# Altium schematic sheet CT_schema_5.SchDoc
size 308 x 315 mm
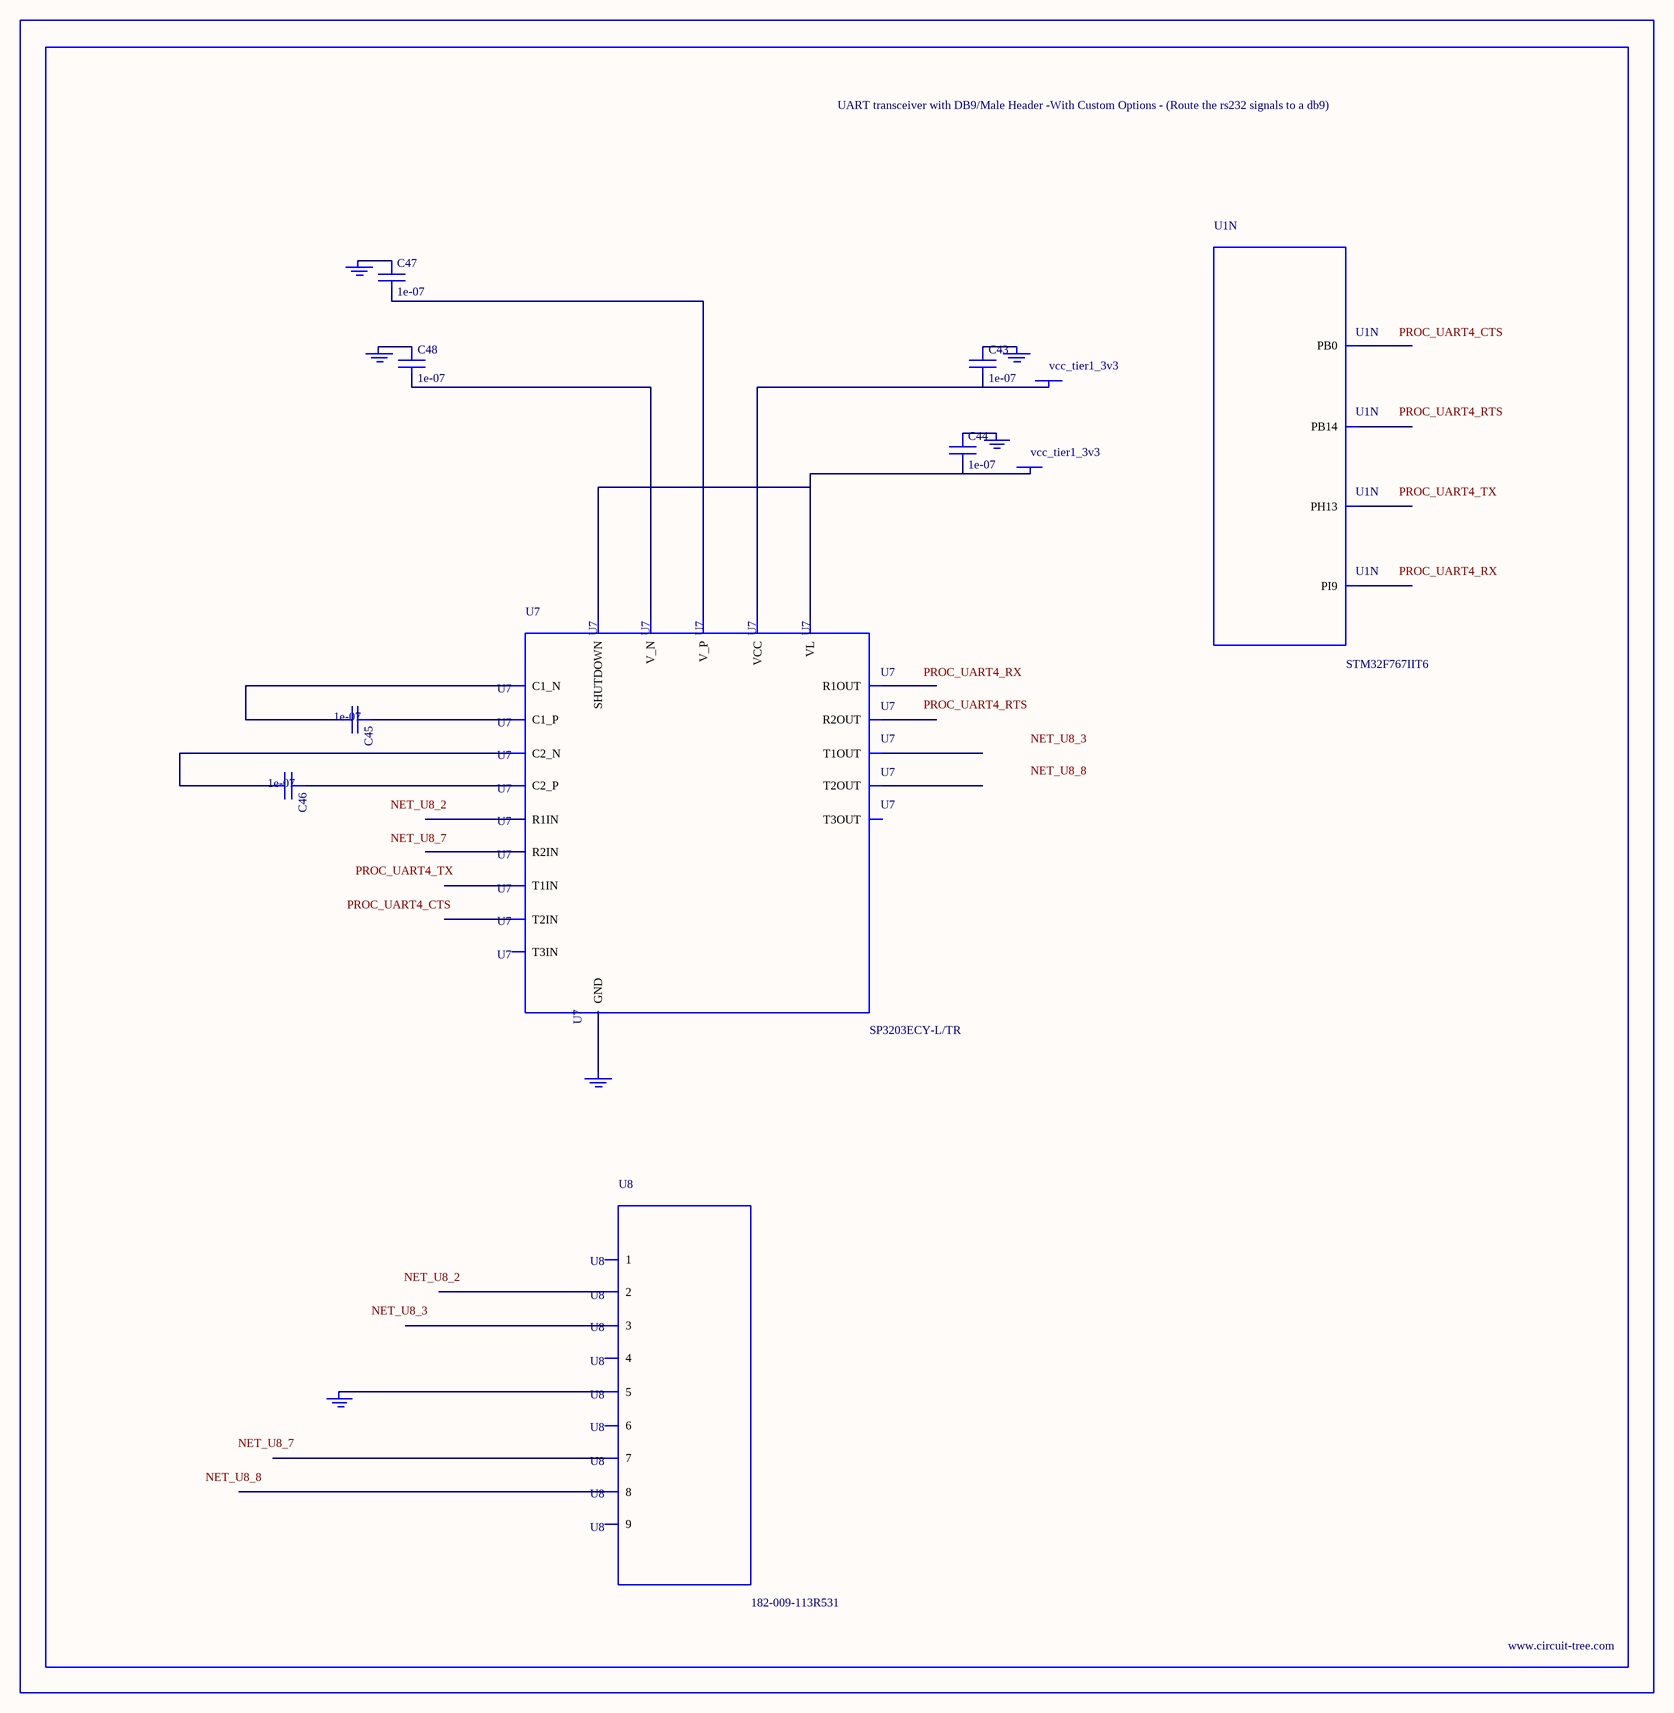
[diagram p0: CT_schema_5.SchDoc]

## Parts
BORDER4  (no value)
C43  1e-07  [C0402]
C44  1e-07  [C0402]
C45  1e-07  [C0402]
C46  1e-07  [C0402]
C47  1e-07  [C0402]
C48  1e-07  [C0402]
GND_INSTANCE_4_0  (no value)
GND_INSTANCE_4_1  (no value)
GND_INSTANCE_4_2  (no value)
GND_INSTANCE_4_3  (no value)
GND_INSTANCE_4_4  (no value)
GND_INSTANCE_4_5  (no value)
POWER_INSTANCE_4_0  vcc_tier1_3v3
POWER_INSTANCE_4_1  vcc_tier1_3v3
U1  STM32F767IIT6  [LQFP176]  (part N of 15)
U7  SP3203ECY-L/TR  [TSSOP20-I]
U8  182-009-113R531  [182-009-MALE]

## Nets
NetC43_1: C43.1 GND_INSTANCE_4_3.0(GND)
NetC43_2: C43.2 POWER_INSTANCE_4_1.0(PWR) U7.19(VCC)
NetC44_1: C44.1 GND_INSTANCE_4_2.0(GND)
NetC44_2: C44.2 POWER_INSTANCE_4_0.0(PWR) U7.12(VL) U7.20(SHUTDOWN)
NetC45_1: C45.1 U7.1(C1_P)
NetC45_2: C45.2 U7.3(C1_N)
NetC46_1: C46.1 U7.4(C2_P)
NetC46_2: C46.2 U7.5(C2_N)
NetC47_1: C47.1 GND_INSTANCE_4_0.0(GND)
NetC47_2: C47.2 U7.2(V_P)
NetC48_1: C48.1 GND_INSTANCE_4_1.0(GND)
NetC48_2: C48.2 U7.6(V_N)
NetGND_INSTANCE_4_4_0: GND_INSTANCE_4_4.0(GND) U7.18(GND)
NetGND_INSTANCE_4_5_0: GND_INSTANCE_4_5.0(GND) U8.5

Not connected (* = marked no-connect by the designer): U1 11(PI9) 56(PB0) 94(PB14) 128(PH13); U7 7(T1IN) 8(T2IN) 9(T3IN) 10(R2OUT) 11(R1OUT) 13(R2IN) 14(R1IN) 15(T3OUT) 16(T2OUT) 17(T1OUT); U8 1 2 3 4 6 7 8 9

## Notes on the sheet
- Labels drawn without touching a wire or pin: NET_U8_2, NET_U8_3, NET_U8_7, NET_U8_8, PROC_UART4_CTS, PROC_UART4_RTS, PROC_UART4_RX, PROC_UART4_TX

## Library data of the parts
BORDER4 = BORDER_PAGE4
C43-C48 = C0402C104K3RACTU
GND_INSTANCE_4_0-GND_INSTANCE_4_5 = GND
POWER_INSTANCE_4_0 POWER_INSTANCE_4_1 = PWR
